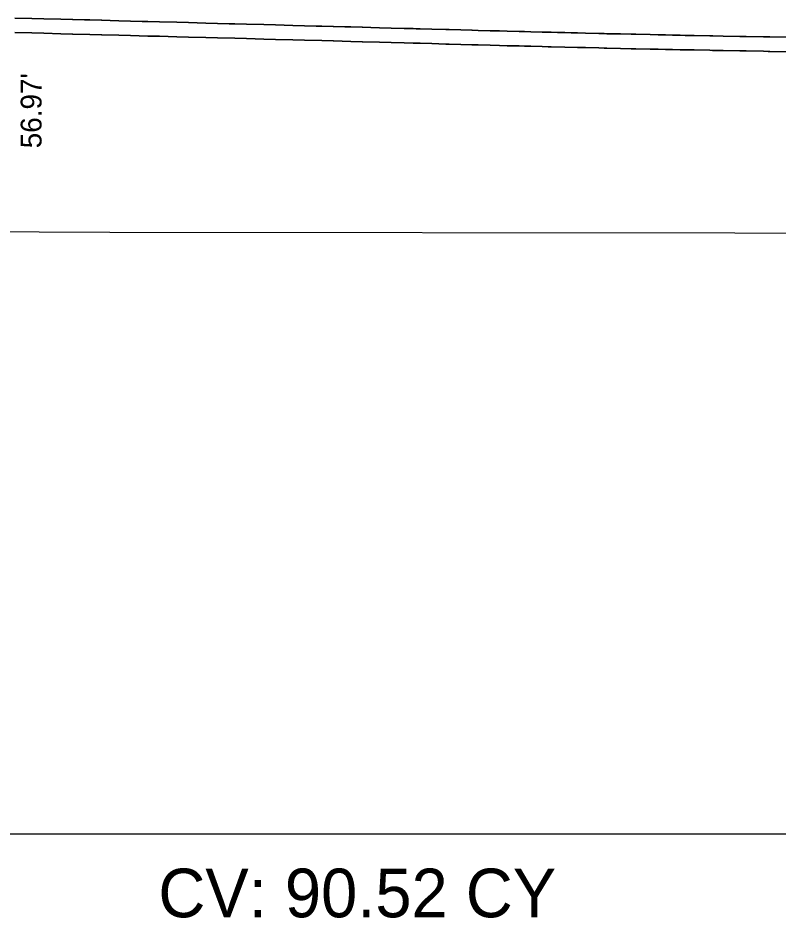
# Model space of a CAD drawing. Extents: x -26 to 4403, y -13 to 9578.
# Drawn here: x 1307.11 to 1333.35, y 7497.1 to 7528.16 of the extents above; entities that cross this region are included whole.
import ezdxf

# ---------------------------------------------------------------- set-up
doc = ezdxf.new("R2010")
doc.units = 0
for name, color, linetype in [('CONST_LV3', 7, 'Continuous'), ('DTM_P_FINISHED_GRADE', 7, 'Continuous'), ('DTM_X_GROUND', 7, 'Continuous'), ('XS_CELL', 7, 'Continuous'), ('XS_M_SHAPES_EARTHWORK', 7, 'Continuous'), ('XS_P_DR_GRAVEL', 7, 'Continuous'), ('XS_P_TX_CLEARZONE', 7, 'Continuous'), ('XS_SHEET_EW_TX_VOLUME', 7, 'Continuous')]:
    doc.layers.add(name, color=color, linetype=linetype)

msp = doc.modelspace()

# ---------------------------------------------------------------- linework, layer by layer
at = {"layer": 'CONST_LV3'}
msp.add_lwpolyline([(1307, 7528.164), (1307.595, 7528.148), (1308, 7528.137), (1308.595, 7528.121), (1309, 7528.11), (1309.405, 7528.1), (1310, 7528.084), (1310.596, 7528.068), (1311, 7528.057), (1311.404, 7528.047), (1312, 7528.031), (1312.596, 7528.015), (1313, 7528.004), (1313.596, 7527.988), (1314, 7527.978), (1314.404, 7527.967), (1315, 7527.951), (1315.597, 7527.935), (1316, 7527.925), (1316.597, 7527.909), (1317, 7527.898), (1317.403, 7527.887), (1318, 7527.872), (1318.403, 7527.861), (1319, 7527.845), (1319.597, 7527.829), (1320, 7527.818), (1320.449, 7527.806), (1320.755, 7527.798), (1320.76, 7527.798), (1320.863, 7527.795), (1320.959, 7527.792), (1321, 7527.79), (1321.403, 7527.78), (1321.882, 7527.766), (1322, 7527.762), (1322.406, 7527.752), (1322.787, 7527.741), (1322.999, 7527.734), (1323.41, 7527.724), (1323.741, 7527.716), (1323.997, 7527.708), (1324.416, 7527.698), (1324.603, 7527.692), (1324.994, 7527.682), (1325.423, 7527.673), (1325.516, 7527.669), (1325.735, 7527.664), (1326.208, 7527.653), (1326.431, 7527.648), (1326.708, 7527.64), (1327.165, 7527.631), (1327.352, 7527.625), (1327.438, 7527.622), (1327.913, 7527.613), (1328.278, 7527.604), (1328.446, 7527.6), (1328.941, 7527.591), (1329.211, 7527.584), (1329.452, 7527.579), (1329.971, 7527.569), (1330.15, 7527.565), (1330.419, 7527.56), (1330.726, 7527.554), (1331.002, 7527.549), (1331.096, 7527.547), (1331.459, 7527.54), (1332.033, 7527.53), (1332.052, 7527.529), (1332.25, 7527.525), (1332.858, 7527.515), (1333.017, 7527.512), (1333.065, 7527.511), (1333.712, 7527.501)], dxfattribs=at)
at = {"layer": 'DTM_P_FINISHED_GRADE'}
msp.add_lwpolyline([(1307.002, 7528.163), (1307.596, 7528.148), (1308, 7528.137), (1308.002, 7528.137), (1308.597, 7528.121), (1309, 7528.11), (1309.002, 7528.11), (1309.597, 7528.095), (1310, 7528.084), (1310.002, 7528.084), (1310.597, 7528.068), (1311, 7528.057), (1311.002, 7528.057), (1311.597, 7528.042), (1312, 7528.031), (1312.002, 7528.031), (1312.598, 7528.015), (1313, 7528.004), (1313.002, 7528.004), (1313.598, 7527.988), (1314, 7527.978), (1314.002, 7527.978), (1314.598, 7527.962), (1315, 7527.951), (1315.002, 7527.951), (1315.598, 7527.935), (1316, 7527.925), (1316.002, 7527.925), (1316.598, 7527.909), (1317, 7527.898), (1317.002, 7527.898), (1317.599, 7527.882), (1318, 7527.872), (1318.002, 7527.872), (1318.599, 7527.856), (1319, 7527.845), (1319.002, 7527.845), (1319.599, 7527.829), (1320, 7527.818), (1320.002, 7527.818), (1320.45, 7527.806), (1320.755, 7527.798), (1320.76, 7527.798), (1320.863, 7527.795), (1320.959, 7527.792), (1320.961, 7527.792), (1321.002, 7527.79), (1321.403, 7527.78), (1321.882, 7527.766), (1321.883, 7527.766), (1322.001, 7527.762), (1322.406, 7527.752), (1322.787, 7527.741), (1322.789, 7527.741), (1323.001, 7527.734), (1323.41, 7527.724), (1323.741, 7527.716), (1323.743, 7527.716), (1323.999, 7527.708), (1324.416, 7527.698), (1324.603, 7527.692), (1324.605, 7527.692), (1324.818, 7527.687), (1325.209, 7527.677), (1325.423, 7527.673), (1325.516, 7527.669), (1325.517, 7527.669), (1325.99, 7527.658), (1326.431, 7527.648), (1326.433, 7527.648), (1326.71, 7527.64), (1327.165, 7527.631), (1327.352, 7527.625), (1327.354, 7527.625), (1327.44, 7527.622), (1327.913, 7527.613), (1328.278, 7527.604), (1328.28, 7527.604), (1328.447, 7527.6), (1328.941, 7527.591), (1329.211, 7527.584), (1329.212, 7527.584), (1329.469, 7527.58), (1329.71, 7527.574), (1329.971, 7527.569), (1330.15, 7527.565), (1330.152, 7527.565), (1330.458, 7527.559), (1331.002, 7527.549), (1331.096, 7527.547), (1331.099, 7527.547), (1331.461, 7527.54), (1332.033, 7527.53), (1332.052, 7527.529), (1332.054, 7527.529), (1332.252, 7527.525), (1332.858, 7527.515), (1333.017, 7527.512), (1333.019, 7527.512), (1333.067, 7527.511), (1333.712, 7527.501)], dxfattribs=at)
at = {"layer": 'DTM_X_GROUND'}
msp.add_lwpolyline([(1159.518, 7517.394), (1200.052, 7515.401), (1217.74, 7513.76), (1222.892, 7513.417), (1226.763, 7513.627), (1241.699, 7515.779), (1244.696, 7517.139), (1249.906, 7516.828), (1249.956, 7516.833), (1276.709, 7519.611), (1283.124, 7519.79), (1294.202, 7520.766), (1295.632, 7520.835), (1310.279, 7520.767), (1331.863, 7520.749), (1369.14, 7520.527), (1389.173, 7520.495), (1400, 7520.407)], dxfattribs=at)
at = {"layer": 'XS_CELL'}
msp.add_line((1250, 7500), (1400, 7500), dxfattribs=at)
at = {"layer": 'XS_M_SHAPES_EARTHWORK'}
for points in [[(1333.712, 7527.001), (1333.067, 7527.011), (1333.019, 7527.012), (1333.017, 7527.012), (1332.858, 7527.015), (1332.252, 7527.025), (1332.054, 7527.029), (1332.052, 7527.029), (1332.033, 7527.03), (1331.461, 7527.04), (1331.099, 7527.047), (1331.096, 7527.047), (1331.002, 7527.049), (1330.458, 7527.059), (1330.152, 7527.065), (1330.15, 7527.065), (1329.971, 7527.069), (1329.71, 7527.074), (1329.469, 7527.08), (1329.212, 7527.084), (1329.211, 7527.084), (1328.941, 7527.091), (1328.447, 7527.1), (1328.28, 7527.104), (1328.278, 7527.104), (1327.913, 7527.113), (1327.44, 7527.122), (1327.354, 7527.125), (1327.352, 7527.125), (1327.165, 7527.131), (1326.71, 7527.14), (1326.433, 7527.148), (1326.431, 7527.148), (1325.99, 7527.158), (1325.517, 7527.169), (1325.516, 7527.169), (1325.423, 7527.173), (1325.209, 7527.177), (1324.818, 7527.187), (1324.605, 7527.192), (1324.603, 7527.192), (1324.416, 7527.198), (1323.999, 7527.208), (1323.743, 7527.216), (1323.741, 7527.216), (1323.41, 7527.224), (1323.001, 7527.234), (1322.789, 7527.241), (1322.787, 7527.241), (1322.406, 7527.252), (1322.001, 7527.262), (1321.883, 7527.266), (1321.882, 7527.266), (1321.403, 7527.28), (1321.002, 7527.29), (1320.961, 7527.292), (1320.959, 7527.292), (1320.863, 7527.295), (1320.76, 7527.298), (1320.755, 7527.298), (1320.45, 7527.306), (1320.002, 7527.318), (1320, 7527.318), (1319.599, 7527.329), (1319.002, 7527.345), (1319, 7527.345), (1318.599, 7527.356), (1318.002, 7527.372), (1318, 7527.372), (1317.599, 7527.382), (1317.002, 7527.398), (1317, 7527.398), (1316.598, 7527.409), (1316.002, 7527.425), (1316, 7527.425), (1315.598, 7527.435), (1315.002, 7527.451), (1315, 7527.451), (1314.598, 7527.462), (1314.002, 7527.478), (1314, 7527.478), (1313.598, 7527.488), (1313.002, 7527.504), (1313, 7527.504), (1312.598, 7527.515), (1312.002, 7527.531), (1312, 7527.531), (1311.597, 7527.542), (1311.002, 7527.557), (1311, 7527.557), (1310.597, 7527.568), (1310.002, 7527.584), (1310, 7527.584), (1309.597, 7527.595), (1309.002, 7527.61), (1309, 7527.61), (1308.597, 7527.621), (1308.002, 7527.637), (1308, 7527.637), (1307.596, 7527.648), (1307.002, 7527.663)], [(1249.956, 7516.833), (1276.709, 7519.611), (1283.124, 7519.79), (1294.202, 7520.766), (1295.632, 7520.835), (1310.279, 7520.767), (1331.863, 7520.749), (1369.14, 7520.527)]]:
    msp.add_lwpolyline(points, dxfattribs=at)
at = {"layer": 'XS_P_DR_GRAVEL'}
for points in [[(1333.712, 7527.501), (1333.067, 7527.511), (1333.019, 7527.512), (1333.017, 7527.512), (1332.858, 7527.515), (1332.252, 7527.525), (1332.054, 7527.529), (1332.052, 7527.529), (1332.033, 7527.53), (1331.461, 7527.54), (1331.099, 7527.547), (1331.096, 7527.547), (1331.002, 7527.549), (1330.458, 7527.559), (1330.152, 7527.565), (1330.15, 7527.565), (1329.971, 7527.569), (1329.71, 7527.574), (1329.469, 7527.58), (1329.212, 7527.584), (1329.211, 7527.584), (1328.941, 7527.591), (1328.447, 7527.6), (1328.28, 7527.604), (1328.278, 7527.604), (1327.913, 7527.613), (1327.44, 7527.622), (1327.354, 7527.625), (1327.352, 7527.625), (1327.165, 7527.631), (1326.71, 7527.64), (1326.433, 7527.648), (1326.431, 7527.648), (1325.99, 7527.658), (1325.517, 7527.669), (1325.516, 7527.669), (1325.423, 7527.673), (1325.209, 7527.677), (1324.818, 7527.687), (1324.605, 7527.692), (1324.603, 7527.692), (1324.416, 7527.698), (1323.999, 7527.708), (1323.743, 7527.716), (1323.741, 7527.716), (1323.41, 7527.724), (1323.001, 7527.734), (1322.789, 7527.741), (1322.787, 7527.741), (1322.406, 7527.752), (1322.001, 7527.762), (1321.883, 7527.766), (1321.882, 7527.766), (1321.403, 7527.78), (1321.002, 7527.79), (1320.961, 7527.792), (1320.959, 7527.792), (1320.863, 7527.795), (1320.76, 7527.798), (1320.755, 7527.798), (1320.45, 7527.806), (1320.002, 7527.818), (1320, 7527.818), (1319.599, 7527.829), (1319.002, 7527.845), (1319, 7527.845), (1318.599, 7527.856), (1318.002, 7527.872), (1318, 7527.872), (1317.599, 7527.882), (1317.002, 7527.898), (1317, 7527.898), (1316.598, 7527.909), (1316.002, 7527.925), (1316, 7527.925), (1315.598, 7527.935), (1315.002, 7527.951), (1315, 7527.951), (1314.598, 7527.962), (1314.002, 7527.978), (1314, 7527.978), (1313.598, 7527.988), (1313.002, 7528.004), (1313, 7528.004), (1312.598, 7528.015), (1312.002, 7528.031), (1312, 7528.031), (1311.597, 7528.042), (1311.002, 7528.057), (1311, 7528.057), (1310.597, 7528.068), (1310.002, 7528.084), (1310, 7528.084), (1309.597, 7528.095), (1309.002, 7528.11), (1309, 7528.11), (1308.597, 7528.121), (1308.002, 7528.137), (1308, 7528.137), (1307.596, 7528.148), (1307.002, 7528.163)], [(1307.002, 7527.663), (1307.596, 7527.648), (1308, 7527.637), (1308.002, 7527.637), (1308.597, 7527.621), (1309, 7527.61), (1309.002, 7527.61), (1309.597, 7527.595), (1310, 7527.584), (1310.002, 7527.584), (1310.597, 7527.568), (1311, 7527.557), (1311.002, 7527.557), (1311.597, 7527.542), (1312, 7527.531), (1312.002, 7527.531), (1312.598, 7527.515), (1313, 7527.504), (1313.002, 7527.504), (1313.598, 7527.488), (1314, 7527.478), (1314.002, 7527.478), (1314.598, 7527.462), (1315, 7527.451), (1315.002, 7527.451), (1315.598, 7527.435), (1316, 7527.425), (1316.002, 7527.425), (1316.598, 7527.409), (1317, 7527.398), (1317.002, 7527.398), (1317.599, 7527.382), (1318, 7527.372), (1318.002, 7527.372), (1318.599, 7527.356), (1319, 7527.345), (1319.002, 7527.345), (1319.599, 7527.329), (1320, 7527.318), (1320.002, 7527.318), (1320.45, 7527.306), (1320.755, 7527.298), (1320.76, 7527.298), (1320.863, 7527.295), (1320.959, 7527.292), (1320.961, 7527.292), (1321.002, 7527.29), (1321.403, 7527.28), (1321.882, 7527.266), (1321.883, 7527.266), (1322.001, 7527.262), (1322.406, 7527.252), (1322.787, 7527.241), (1322.789, 7527.241), (1323.001, 7527.234), (1323.41, 7527.224), (1323.741, 7527.216), (1323.743, 7527.216), (1323.999, 7527.208), (1324.416, 7527.198), (1324.603, 7527.192), (1324.605, 7527.192), (1324.818, 7527.187), (1325.209, 7527.177), (1325.423, 7527.173), (1325.516, 7527.169), (1325.517, 7527.169), (1325.99, 7527.158), (1326.431, 7527.148), (1326.433, 7527.148), (1326.71, 7527.14), (1327.165, 7527.131), (1327.352, 7527.125), (1327.354, 7527.125), (1327.44, 7527.122), (1327.913, 7527.113), (1328.278, 7527.104), (1328.28, 7527.104), (1328.447, 7527.1), (1328.941, 7527.091), (1329.211, 7527.084), (1329.212, 7527.084), (1329.469, 7527.08), (1329.71, 7527.074), (1329.971, 7527.069), (1330.15, 7527.065), (1330.152, 7527.065), (1330.458, 7527.059), (1331.002, 7527.049), (1331.096, 7527.047), (1331.099, 7527.047), (1331.461, 7527.04), (1332.033, 7527.03), (1332.052, 7527.029), (1332.054, 7527.029), (1332.252, 7527.025), (1332.858, 7527.015), (1333.017, 7527.012), (1333.019, 7527.012), (1333.067, 7527.011), (1333.712, 7527.001)]]:
    msp.add_lwpolyline(points, dxfattribs=at)

# ---------------------------------------------------------------- texts
at = {"layer": 'XS_P_TX_CLEARZONE'}
msp.add_text("56.97'", height=0.72, rotation=90, dxfattribs=at).set_placement((1307.926, 7523.666))
msp.add_text("56.97'", height=0.72, rotation=90, dxfattribs=at).set_placement((1307.926, 7523.666))
msp.add_text("56.97'", height=0.72, rotation=90, dxfattribs=at).set_placement((1307.926, 7523.666))
at = {"layer": 'XS_SHEET_EW_TX_VOLUME'}
msp.add_text('CV: 90.52 CY', height=1.68, dxfattribs=at).set_placement((1311.959, 7497.12))

doc.saveas('drawing.dxf')
